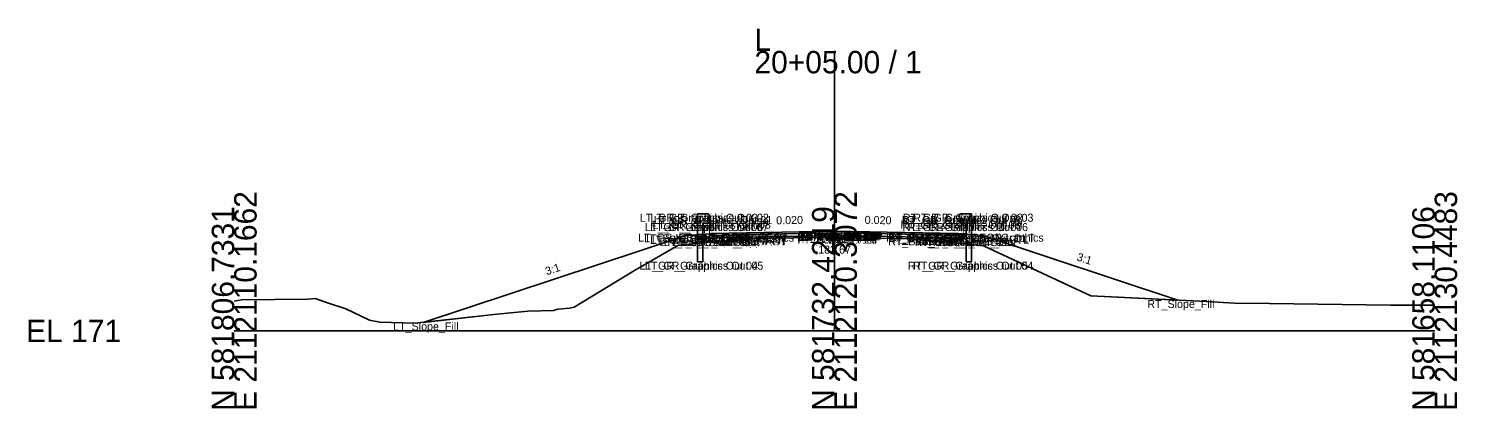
# Model space of a CAD drawing. Extents: x -486 to 1153, y -333 to 9539.
# Drawn here: x 974.3 to 1152.8, y 990.3 to 1037.8 of the extents above; entities that cross this region are included whole.
import ezdxf

# ---------------------------------------------------------------- set-up
doc = ezdxf.new("R2010")
doc.units = 0
for name, color, linetype in [('Default', 7, 'Continuous'), ('Exist Cross Section Cell', 7, 'Continuous'), ('Exist XS Ground Line', 7, 'Continuous'), ('Prop CMT Guardrail Graphics', 7, 'Continuous'), ('Prop CMT Pvmt Course 1', 7, 'Continuous'), ('Prop CMT Pvmt Course 2', 7, 'Continuous'), ('Prop CMT Pvmt Course 3', 7, 'Continuous'), ('Prop CMT Pvmt Surface', 7, 'Continuous'), ('Prop CMT Pvmt Surface Shoulder', 7, 'Continuous'), ('Prop CMT Shld Paved Course 1', 7, 'Continuous'), ('Prop CMT Shld Paved Course 2', 7, 'Continuous'), ('Prop CMT Shld Paved Course 3', 7, 'Continuous'), ('Prop CMT Slope Grass', 7, 'Continuous'), ('Prop CMT Subgrade Earthwork', 7, 'Continuous'), ('Prop XS Earthwork Shape', 7, 'Continuous'), ('Prop XS SE Text', 7, 'Continuous'), ('Prop XS Side Slope Text', 7, 'Continuous'), ('Scratch_Level_0', 7, 'Continuous')]:
    doc.layers.add(name, color=color, linetype=linetype)

msp = doc.modelspace()

# ---------------------------------------------------------------- linework, layer by layer
at = {"layer": 'Exist Cross Section Cell'}
for p, q in [((1075, 1000), (1075, 1035.02)), ((1000, 1000), (1075, 1000)), ((1075, 1000), (1150, 1000))]:
    msp.add_line(p, q, dxfattribs=at)
at = {"layer": 'Exist XS Ground Line'}
for p, q in [((1050.01, 1007.57), (1055.43, 1010.69)), ((1055.43, 1010.69), (1056.8, 1010.84)), ((1056.8, 1010.84), (1061.48, 1011.28)), ((1061.48, 1011.28), (1065.33, 1011.56)), ((1065.33, 1011.56), (1069.93, 1011.64)), ((1069.93, 1011.64), (1074.88, 1011.67)), ((1074.88, 1011.67), (1079.6, 1011.61)), ((1079.6, 1011.61), (1084.63, 1011.52)), ((1084.63, 1011.52), (1093.63, 1010.63)), ((1093.63, 1010.63), (1107.03, 1004.41)), ((1042.46, 1002.97), (1050.01, 1007.57)), ((1000, 1003.71), (1000.47, 1003.79)), ((1000.47, 1003.79), (1000.93, 1003.89)), ((1000.93, 1003.89), (1009.15, 1003.96)), ((1009.15, 1003.96), (1010.11, 1004.04)), ((1010.11, 1004.04), (1011.52, 1003.56)), ((1011.52, 1003.56), (1013.95, 1002.77)), ((1107.03, 1004.41), (1121.47, 1003.69)), ((1121.47, 1003.69), (1125, 1003.46)), ((1125, 1003.46), (1129.37, 1003.42)), ((1129.37, 1003.42), (1144.47, 1003.24)), ((1013.95, 1002.77), (1016.92, 1001.36)), ((1022.63, 1000.96), (1032.46, 1002.06)), ((1032.46, 1002.06), (1036.69, 1002.47)), ((1036.69, 1002.47), (1039.88, 1002.56)), ((1039.88, 1002.56), (1040.42, 1002.72)), ((1040.42, 1002.72), (1041.89, 1002.85)), ((1041.89, 1002.85), (1042.46, 1002.97)), ((1144.47, 1003.24), (1150, 1003.23)), ((1016.92, 1001.36), (1018.18, 1001.1)), ((1018.18, 1001.1), (1022.63, 1000.96))]:
    msp.add_line(p, q, dxfattribs=at)
at = {"layer": 'Prop CMT Guardrail Graphics'}
for points in [[(1057.88, 1008.66), (1057.88, 1014.66)], [(1057.88, 1014.66), (1059.21, 1014.66), (1059.48, 1014.37)], [(1059.48, 1014.37), (1059.21, 1014.07)], [(1059.21, 1014.07), (1059.48, 1013.78)], [(1092.12, 1014.66), (1090.79, 1014.66), (1090.52, 1014.37)], [(1090.52, 1014.37), (1090.79, 1014.07)], [(1090.79, 1014.07), (1090.52, 1013.78)], [(1092.12, 1008.66), (1092.12, 1014.66)], [(1059.48, 1013.78), (1059.21, 1013.49), (1058.55, 1013.49)], [(1058.55, 1013.49), (1058.55, 1008.66)], [(1090.52, 1013.78), (1090.79, 1013.49), (1091.45, 1013.49)], [(1091.45, 1013.49), (1091.45, 1008.66)], [(1058.55, 1008.66), (1057.88, 1008.66)], [(1091.45, 1008.66), (1092.12, 1008.66)]]:
    msp.add_lwpolyline(points, dxfattribs=at)
at = {"layer": 'Prop CMT Pvmt Course 1'}
for points in [[(1075, 1012.47), (1064, 1012.25)], [(1075, 1012.27), (1075, 1012.47)], [(1075, 1012.47), (1086, 1012.25)], [(1075, 1012.27), (1075, 1012.47)], [(1064, 1012.05), (1075, 1012.27)], [(1064, 1012.25), (1064, 1012.05)], [(1086, 1012.05), (1075, 1012.27)], [(1086, 1012.25), (1086, 1012.05)]]:
    msp.add_lwpolyline(points, dxfattribs=at)
msp.add_lwpolyline([(1075, 1012.27), (1075, 1012.35), (1075, 1012.35), (1075, 1012.27)], close=True, dxfattribs=at)
msp.add_lwpolyline([(1075, 1012.27), (1075, 1012.35), (1075, 1012.35), (1075, 1012.27)], close=True, dxfattribs=at)
at = {"layer": 'Prop CMT Pvmt Course 2'}
for points in [[(1075, 1012.27), (1064, 1012.05)], [(1064, 1012.05), (1064, 1011.71)], [(1064, 1011.71), (1075, 1011.93)], [(1075, 1011.93), (1075, 1012.27)], [(1075, 1011.93), (1075, 1012.27)], [(1075, 1012.27), (1086, 1012.05)], [(1086, 1011.71), (1075, 1011.93)], [(1086, 1012.05), (1086, 1011.71)]]:
    msp.add_lwpolyline(points, dxfattribs=at)
at = {"layer": 'Prop CMT Pvmt Course 3'}
for points in [[(1075, 1011.93), (1064, 1011.71)], [(1064, 1011.71), (1064, 1011.71)], [(1075, 1011.93), (1075, 1011.93)], [(1075, 1011.93), (1086, 1011.71)], [(1075, 1011.93), (1075, 1011.93)], [(1086, 1011.71), (1086, 1011.71)]]:
    msp.add_lwpolyline(points, dxfattribs=at)
at = {"layer": 'Prop CMT Pvmt Surface'}
for points in [[(1075, 1012.47), (1064, 1012.25)], [(1075, 1012.47), (1086, 1012.25)]]:
    msp.add_lwpolyline(points, dxfattribs=at)
at = {"layer": 'Prop CMT Pvmt Surface Shoulder'}
for points in [[(1064, 1012.25), (1059.58, 1012.17)], [(1086, 1012.25), (1090.42, 1012.17)]]:
    msp.add_lwpolyline(points, dxfattribs=at)
at = {"layer": 'Prop CMT Shld Paved Course 1'}
for points in [[(1064, 1012.25), (1059.58, 1012.17), (1059.37, 1011.95)], [(1059.37, 1011.95), (1064, 1012.05)], [(1064, 1012.05), (1064, 1012.25)], [(1086, 1012.25), (1090.42, 1012.17), (1090.63, 1011.95)], [(1086, 1012.05), (1086, 1012.25)], [(1090.63, 1011.95), (1086, 1012.05)]]:
    msp.add_lwpolyline(points, dxfattribs=at)
at = {"layer": 'Prop CMT Shld Paved Course 2'}
for points in [[(1064, 1012.05), (1059.37, 1011.95), (1059.03, 1011.61)], [(1059.03, 1011.61), (1064, 1011.71)], [(1064, 1011.71), (1064, 1012.05)], [(1086, 1012.05), (1090.63, 1011.95), (1090.97, 1011.61)], [(1086, 1011.71), (1086, 1012.05)], [(1090.97, 1011.61), (1086, 1011.71)]]:
    msp.add_lwpolyline(points, dxfattribs=at)
at = {"layer": 'Prop CMT Shld Paved Course 3'}
for points in [[(1064, 1011.71), (1059.03, 1011.61)], [(1059.03, 1011.61), (1059.03, 1011.61), (1059.03, 1011.61)], [(1064, 1011.71), (1064, 1011.71)], [(1086, 1011.71), (1090.97, 1011.61)], [(1086, 1011.71), (1086, 1011.71)], [(1090.97, 1011.61), (1090.97, 1011.61), (1090.97, 1011.61)]]:
    msp.add_lwpolyline(points, dxfattribs=at)
at = {"layer": 'Prop CMT Slope Grass'}
for points in [[(1056.48, 1011.92), (1023.62, 1001.07)], [(1059.48, 1012.16), (1056.48, 1011.92)], [(1059.58, 1012.17), (1059.48, 1012.16)], [(1090.42, 1012.17), (1090.52, 1012.16)], [(1090.52, 1012.16), (1093.52, 1011.92)], [(1093.52, 1011.92), (1117.91, 1003.87)]]:
    msp.add_lwpolyline(points, dxfattribs=at)
at = {"layer": 'Prop CMT Subgrade Earthwork'}
for points in [[(1059.03, 1011.61), (1058.56, 1012.08)], [(1064, 1011.71), (1059.03, 1011.61)], [(1075, 1011.93), (1064, 1011.71)], [(1075, 1011.93), (1086, 1011.71)], [(1086, 1011.71), (1090.97, 1011.61)], [(1090.97, 1011.61), (1091.44, 1012.08)]]:
    msp.add_lwpolyline(points, dxfattribs=at)
at = {"layer": 'Prop XS Earthwork Shape'}
msp.add_lwpolyline([(1091.44, 1012.08), (1093.52, 1011.92), (1117.91, 1003.87), (1107.03, 1004.41), (1093.63, 1010.63), (1084.63, 1011.52), (1079.6, 1011.61), (1074.88, 1011.67), (1069.93, 1011.64), (1065.33, 1011.56), (1061.48, 1011.28), (1056.8, 1010.84), (1055.43, 1010.69), (1050.01, 1007.57), (1042.46, 1002.97), (1041.89, 1002.85), (1040.42, 1002.72), (1039.88, 1002.56), (1036.69, 1002.47), (1032.46, 1002.06), (1023.62, 1001.07), (1056.48, 1011.92), (1058.56, 1012.08), (1059.03, 1011.61), (1064, 1011.71), (1075, 1011.93), (1086, 1011.71), (1090.97, 1011.61)], close=True, dxfattribs=at)

# ---------------------------------------------------------------- texts
at = {"layer": 'Default'}
for s, height, p in [('182.67', 1, (1072.97, 1009.67)), ('-', 0.0001, (1000, 1000))]:
    msp.add_text(s, height=height, dxfattribs=at).set_placement(p)
at = {"layer": 'Exist Cross Section Cell'}
for s, p in [('L', (1065, 1035.02)), ('20+05.00 / 1', (1065, 1032.22)), ('EL 171', (974, 998.6))]:
    msp.add_text(s, height=2.8, dxfattribs=at).set_placement(p)
for s, p in [('E 2112110.1662', (1002.8, 990)), ('E 2112120.3072', (1077.8, 990)), ('E 2112130.4483', (1152.8, 990)), ('N 581806.7331', (1000, 990)), ('N 581732.4219', (1075, 990)), ('N 581658.1106', (1150, 990))]:
    msp.add_text(s, height=2.8, rotation=90, dxfattribs=at).set_placement(p)
at = {"layer": 'Prop XS SE Text'}
for rotation, p in [(1.1458, (1067.73, 1013.33)), (358.8542, (1078.77, 1013.4))]:
    msp.add_text('0.020', height=1, rotation=rotation, dxfattribs=at).set_placement(p)
at = {"layer": 'Prop XS Side Slope Text'}
for rotation, p in [(341.7371, (1105.2, 1008.85)), (18.2629, (1039.06, 1006.96))]:
    msp.add_text('3:1', height=1, rotation=rotation, dxfattribs=at).set_placement(p)
at = {"layer": 'Scratch_Level_0'}
for s, p in [('LT_GR_Graphics Out 03', (1050.66, 1013.66)), ('LT_GR_Graphics Out 09', (1051.99, 1013.07)), ('LT_GR_Graphics Out 02', (1052.01, 1013.66)), ('LT_GR_Graphics Out 01', (1052.43, 1013.37)), ('RT_GR_Graphics Out 01', (1083.4, 1013.37)), ('RT_GR_Graphics Out 09', (1083.5, 1013.07)), ('RT_GR_Graphics Out 02', (1083.53, 1013.66)), ('RT_GR_Graphics Out 03', (1084.85, 1013.66)), ('LT_GR_Graphics Out 06', (1051.32, 1012.49)), ('LT_GR_Graphics Out 07', (1051.97, 1012.49)), ('LT_GR_Graphics Out 08', (1052.25, 1012.78)), ('RT_PV2_OEEOP', (1070.33, 1011.27)), ('LT_PV2_OEEOP', (1070.39, 1011.27)), ('RT_PV1_OEEOP', (1070.45, 1011.35)), ('LT_PV1_OEEOP', (1070.51, 1011.35)), ('RT_PV2_IEEOP', (1070.71, 1011.27)), ('LT_PV2_IEEOP', (1070.77, 1011.27)), ('RT_PV1_IEEOP', (1070.83, 1011.35)), ('LT_PV1_IEEOP', (1070.89, 1011.35)), ('PV2_PGL', (1072.35, 1011.27)), ('PV1_PGL', (1072.47, 1011.47)), ('RT_GR_Graphics Out 08', (1083.23, 1012.78)), ('RT_GR_Graphics Out 07', (1083.49, 1012.49)), ('RT_GR_Graphics Out 06', (1084.17, 1012.49)), ('LT_GS_OS_GR_Face_Graphics', (1050.48, 1011.16)), ('LT_Sub_Trench_Out_DLT', (1051.21, 1011.08)), ('LT_GS_OS_CTL', (1051.95, 1010.92)), ('LT_Sub_Trench_Out', (1053.14, 1010.61)), ('LT_PS3_Shelf_Out', (1053.69, 1010.61)), ('LT_PS3_OEOP', (1054.82, 1010.61)), ('LT_PS2_OEOP', (1055.16, 1010.95)), ('LT_PS1_OEOP', (1055.49, 1011.17)), ('LT_PV2_OEOT', (1059.75, 1011.05)), ('LT_PV3_OEOT', (1059.75, 1010.71)), ('LT_Sub_OEOT', (1059.77, 1010.71)), ('LT_PV1_OEOT', (1059.87, 1011.25)), ('RT_PV3_OEEOP', (1070.33, 1010.93)), ('RT_Sub_OEEOP', (1070.36, 1010.93)), ('LT_PV3_OEEOP', (1070.39, 1010.93)), ('LT_Sub_OEEOP', (1070.42, 1010.93)), ('RT_GS_OS_GR_Face_Graphics', (1081.45, 1011.16)), ('RT_PV2_OEOT', (1081.69, 1011.05)), ('RT_PV3_OEOT', (1081.69, 1010.71)), ('RT_Sub_OEOT', (1081.71, 1010.71)), ('RT_PV1_OEOT', (1081.81, 1011.25)), ('RT_Sub_Trench_Out_DLT', (1084.03, 1011.08)), ('RT_Sub_Trench_Out', (1085.02, 1010.61)), ('RT_PS3_Shelf_Out', (1085.57, 1010.61)), ('RT_PS1_OEOP', (1086.26, 1011.17)), ('RT_PS2_OEOP', (1086.36, 1010.95)), ('RT_PS3_OEOP', (1086.7, 1010.61)), ('RT_GS_OS_CTL', (1088.92, 1010.92)), ('LT_GR_Graphics Out 04', (1050.65, 1007.66)), ('LT_GR_Graphics Out 05', (1051.32, 1007.66)), ('RT_GR_Graphics Out 05', (1084.17, 1007.66)), ('RT_GR_Graphics Out 04', (1084.83, 1007.66)), ('RT_Slope_Fill', (1114.09, 1002.87)), ('LT_Slope_Fill', (1019.86, 1000.07))]:
    msp.add_text(s, height=1, dxfattribs=at).set_placement(p)

doc.saveas('drawing.dxf')
